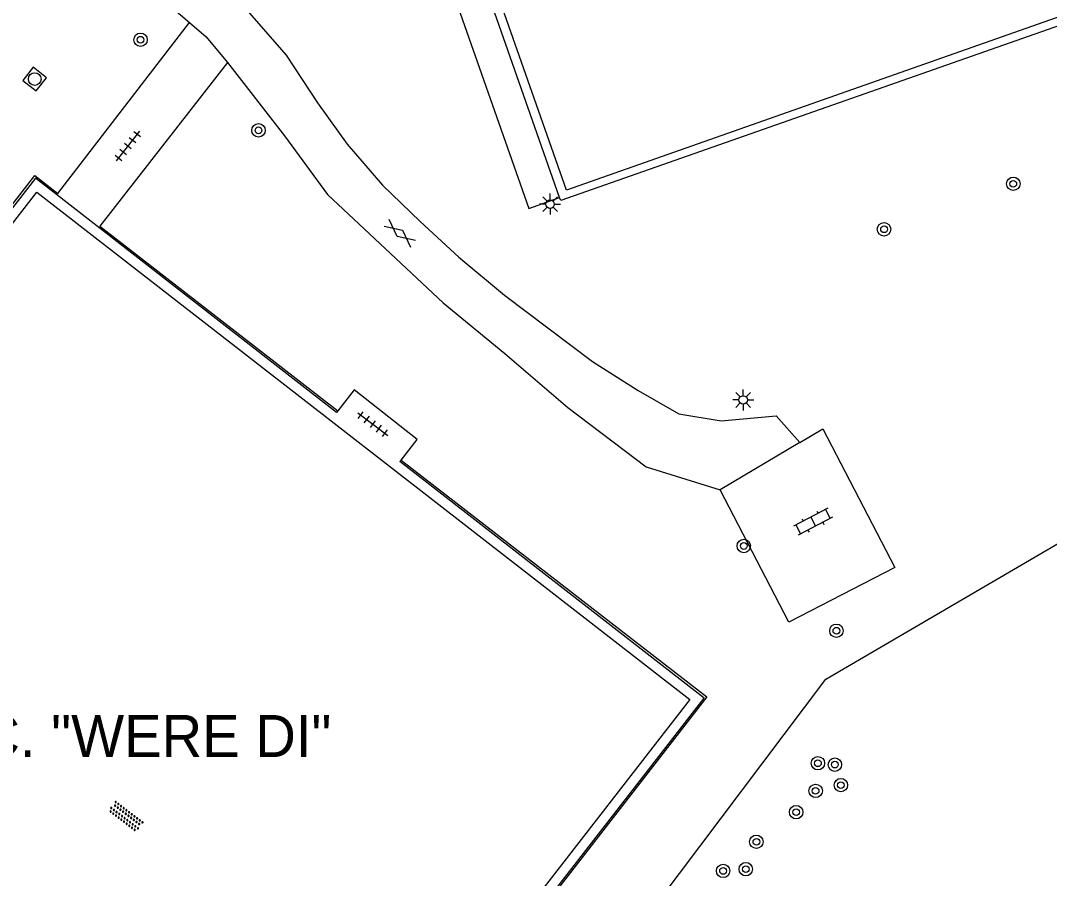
# Model space of a CAD drawing. Extents: x 135990 to 139000, y 393500 to 396000.
# Drawn here: x 136048.3 to 136109.5, y 395713.3 to 395764.3 of the extents above; entities that cross this region are included whole.
import ezdxf

# ---------------------------------------------------------------- set-up
doc = ezdxf.new("R2010")
doc.units = 0
for name, color, linetype in [('gg-afsc-hekwerk', 7, 'Continuous'), ('gg-knt-verharding', 7, 'Continuous'), ('gt-anno-naam bijzondere bebouwing', 7, 'Continuous'), ('gt-symb-boom', 7, 'Continuous'), ('gt-symb-gesloten verharding', 7, 'Continuous'), ('gt-symb-klinker verharding', 7, 'Continuous'), ('gt-symb-lichtmast', 7, 'Continuous'), ('gt-symb-overige verharding', 7, 'Continuous'), ('gt-symb-rioolschacht', 7, 'Continuous'), ('gt-symb-tegel verharding', 7, 'Continuous')]:
    doc.layers.add(name, color=color, linetype=linetype)

# ---------------------------------------------------------------- blocks, each defined once
blk = doc.blocks.new('gt0-BOOM')
at = {"layer": 'gt-symb-boom'}
for radius in [0.4, 0.2]:
    blk.add_circle((0, 0), radius, dxfattribs=at)
blk = doc.blocks.new('gt0-LMAST')
at = {"layer": 'gt-symb-lichtmast'}
for p, q in [((-0.005, 0.246), (-0.005, 0.621)), ((-0.182, 0.173), (-0.447, 0.438)), ((0.172, 0.173), (0.437, 0.438)), ((-0.255, -0.004), (-0.63, -0.004)), ((-0.182, -0.181), (-0.447, -0.446)), ((-0.005, -0.254), (-0.005, -0.629)), ((0.437, -0.446), (0.172, -0.181)), ((0.245, -0.004), (0.62, -0.004))]:
    blk.add_line(p, q, dxfattribs=at)
blk.add_circle((-0.005, -0.004), 0.25, dxfattribs=at)
blk = doc.blocks.new('gt0-KL1')
at = {"layer": 'gt-symb-klinker verharding'}
for p, q in [((-1.15, 0.3), (1.15, 0.3)), ((-1, -0.3), (-1, 0.3)), ((-0.5, 0.3), (-0.5, 0.45)), ((0, -0.3), (0, 0.3)), ((0.5, 0.3), (0.5, 0.45)), ((1, -0.3), (1, 0.3)), ((-1.15, -0.3), (1.15, -0.3)), ((-0.5, -0.45), (-0.5, -0.3)), ((0.5, -0.45), (0.5, -0.3))]:
    blk.add_line(p, q, dxfattribs=at)
blk = doc.blocks.new('gt0-GESVH1')
at = {"layer": 'gt-symb-gesloten verharding'}
for p, q in [((-0.992, -0.261), (0.008, 0.239)), ((0.008, -0.261), (-0.992, 0.239)), ((0.008, 0.239), (1.008, -0.261)), ((1.008, 0.239), (0.008, -0.261))]:
    blk.add_line(p, q, dxfattribs=at)
blk = doc.blocks.new('gt0-TEG1')
at = {"layer": 'gt-symb-tegel verharding'}
for p, q in [((-1.125, 0), (1.125, 0)), ((-0.9, -0.25), (-0.9, 0.25)), ((-0.45, -0.25), (-0.45, 0.25)), ((0, -0.25), (0, 0.25)), ((0.45, -0.25), (0.45, 0.25)), ((0.9, -0.25), (0.9, 0.25))]:
    blk.add_line(p, q, dxfattribs=at)
blk = doc.blocks.new('gt0-RS')
at = {"layer": 'gt-symb-rioolschacht'}
blk.add_lwpolyline([(-0.5, -0.5), (0.5, -0.5), (0.5, 0.5), (-0.5, 0.5)], close=True, dxfattribs=at)
blk.add_circle((0, 0), 0.375, dxfattribs=at)
blk = doc.blocks.new('gt0-OVH')
at = {"layer": 'gt-symb-overige verharding'}
for points in [[(-0.972, 0.298), (-0.967, 0.308), (-0.965, 0.319), (-0.966, 0.33), (-0.971, 0.34), (-0.978, 0.348), (-0.988, 0.353), (-0.999, 0.355), (-1.01, 0.354), (-1.02, 0.349), (-1.028, 0.342), (-1.033, 0.332), (-1.035, 0.321), (-1.034, 0.31), (-1.029, 0.3), (-1.022, 0.292), (-1.012, 0.287), (-1.001, 0.285), (-0.99, 0.286), (-0.98, 0.291)], [(-0.872, 0.106), (-0.867, 0.116), (-0.865, 0.126), (-0.866, 0.137), (-0.871, 0.147), (-0.878, 0.156), (-0.888, 0.161), (-0.899, 0.163), (-0.91, 0.162), (-0.92, 0.157), (-0.928, 0.15), (-0.933, 0.14), (-0.935, 0.129), (-0.934, 0.118), (-0.929, 0.108), (-0.922, 0.1), (-0.912, 0.095), (-0.901, 0.092), (-0.89, 0.094), (-0.88, 0.098)], [(-0.772, 0.298), (-0.767, 0.308), (-0.765, 0.319), (-0.766, 0.33), (-0.771, 0.34), (-0.778, 0.348), (-0.788, 0.353), (-0.799, 0.355), (-0.81, 0.354), (-0.82, 0.349), (-0.828, 0.342), (-0.833, 0.332), (-0.835, 0.321), (-0.834, 0.31), (-0.829, 0.3), (-0.822, 0.292), (-0.812, 0.287), (-0.801, 0.285), (-0.79, 0.286), (-0.78, 0.291)], [(-0.672, 0.106), (-0.667, 0.116), (-0.665, 0.126), (-0.666, 0.137), (-0.671, 0.147), (-0.678, 0.156), (-0.688, 0.161), (-0.699, 0.163), (-0.71, 0.162), (-0.72, 0.157), (-0.728, 0.15), (-0.733, 0.14), (-0.735, 0.129), (-0.734, 0.118), (-0.729, 0.108), (-0.722, 0.1), (-0.712, 0.095), (-0.701, 0.092), (-0.69, 0.094), (-0.68, 0.098)], [(-0.572, 0.298), (-0.567, 0.308), (-0.565, 0.319), (-0.566, 0.33), (-0.571, 0.34), (-0.578, 0.348), (-0.588, 0.353), (-0.599, 0.355), (-0.61, 0.354), (-0.62, 0.349), (-0.628, 0.342), (-0.633, 0.332), (-0.635, 0.321), (-0.634, 0.31), (-0.629, 0.3), (-0.622, 0.292), (-0.612, 0.287), (-0.601, 0.285), (-0.59, 0.286), (-0.58, 0.291)], [(-0.472, 0.106), (-0.467, 0.116), (-0.465, 0.126), (-0.466, 0.137), (-0.471, 0.147), (-0.478, 0.156), (-0.488, 0.161), (-0.499, 0.163), (-0.51, 0.162), (-0.52, 0.157), (-0.528, 0.15), (-0.533, 0.14), (-0.535, 0.129), (-0.534, 0.118), (-0.529, 0.108), (-0.522, 0.1), (-0.512, 0.095), (-0.501, 0.092), (-0.49, 0.094), (-0.48, 0.098)], [(-0.372, 0.298), (-0.367, 0.308), (-0.365, 0.319), (-0.366, 0.33), (-0.371, 0.34), (-0.378, 0.348), (-0.388, 0.353), (-0.399, 0.355), (-0.41, 0.354), (-0.42, 0.349), (-0.428, 0.342), (-0.433, 0.332), (-0.435, 0.321), (-0.434, 0.31), (-0.429, 0.3), (-0.422, 0.292), (-0.412, 0.287), (-0.401, 0.285), (-0.39, 0.286), (-0.38, 0.291)], [(-0.272, 0.106), (-0.267, 0.116), (-0.265, 0.126), (-0.266, 0.137), (-0.271, 0.147), (-0.278, 0.156), (-0.288, 0.161), (-0.299, 0.163), (-0.31, 0.162), (-0.32, 0.157), (-0.328, 0.15), (-0.333, 0.14), (-0.335, 0.129), (-0.334, 0.118), (-0.329, 0.108), (-0.322, 0.1), (-0.312, 0.095), (-0.301, 0.092), (-0.29, 0.094), (-0.28, 0.098)], [(-0.172, 0.298), (-0.167, 0.308), (-0.165, 0.319), (-0.166, 0.33), (-0.171, 0.34), (-0.178, 0.348), (-0.188, 0.353), (-0.199, 0.355), (-0.21, 0.354), (-0.22, 0.349), (-0.228, 0.342), (-0.233, 0.332), (-0.235, 0.321), (-0.234, 0.31), (-0.229, 0.3), (-0.222, 0.292), (-0.212, 0.287), (-0.201, 0.285), (-0.19, 0.286), (-0.18, 0.291)], [(-0.072, 0.106), (-0.067, 0.116), (-0.065, 0.126), (-0.066, 0.137), (-0.071, 0.147), (-0.078, 0.156), (-0.088, 0.161), (-0.099, 0.163), (-0.11, 0.162), (-0.12, 0.157), (-0.128, 0.15), (-0.133, 0.14), (-0.135, 0.129), (-0.134, 0.118), (-0.129, 0.108), (-0.122, 0.1), (-0.112, 0.095), (-0.101, 0.092), (-0.09, 0.094), (-0.08, 0.098)], [(0.028, 0.298), (0.033, 0.308), (0.035, 0.319), (0.034, 0.33), (0.029, 0.34), (0.022, 0.348), (0.012, 0.353), (0.001, 0.355), (-0.01, 0.354), (-0.02, 0.349), (-0.028, 0.342), (-0.033, 0.332), (-0.035, 0.321), (-0.034, 0.31), (-0.029, 0.3), (-0.022, 0.292), (-0.012, 0.287), (-0.001, 0.285), (0.01, 0.286), (0.02, 0.291)], [(0.128, 0.106), (0.133, 0.116), (0.135, 0.126), (0.134, 0.137), (0.129, 0.147), (0.122, 0.156), (0.112, 0.161), (0.101, 0.163), (0.09, 0.162), (0.08, 0.157), (0.072, 0.15), (0.067, 0.14), (0.065, 0.129), (0.066, 0.118), (0.071, 0.108), (0.078, 0.1), (0.088, 0.095), (0.099, 0.092), (0.11, 0.094), (0.12, 0.098)], [(0.228, 0.298), (0.233, 0.308), (0.235, 0.319), (0.234, 0.33), (0.229, 0.34), (0.222, 0.348), (0.212, 0.353), (0.201, 0.355), (0.19, 0.354), (0.18, 0.349), (0.172, 0.342), (0.167, 0.332), (0.165, 0.321), (0.166, 0.31), (0.171, 0.3), (0.178, 0.292), (0.188, 0.287), (0.199, 0.285), (0.21, 0.286), (0.22, 0.291)], [(0.328, 0.106), (0.333, 0.116), (0.335, 0.126), (0.334, 0.137), (0.329, 0.147), (0.322, 0.156), (0.312, 0.161), (0.301, 0.163), (0.29, 0.162), (0.28, 0.157), (0.272, 0.15), (0.267, 0.14), (0.265, 0.129), (0.266, 0.118), (0.271, 0.108), (0.278, 0.1), (0.288, 0.095), (0.299, 0.092), (0.31, 0.094), (0.32, 0.098)], [(0.428, 0.298), (0.433, 0.308), (0.435, 0.319), (0.434, 0.33), (0.429, 0.34), (0.422, 0.348), (0.412, 0.353), (0.401, 0.355), (0.39, 0.354), (0.38, 0.349), (0.372, 0.342), (0.367, 0.332), (0.365, 0.321), (0.366, 0.31), (0.371, 0.3), (0.378, 0.292), (0.388, 0.287), (0.399, 0.285), (0.41, 0.286), (0.42, 0.291)], [(0.528, 0.106), (0.533, 0.116), (0.535, 0.126), (0.534, 0.137), (0.529, 0.147), (0.522, 0.156), (0.512, 0.161), (0.501, 0.163), (0.49, 0.162), (0.48, 0.157), (0.472, 0.15), (0.467, 0.14), (0.465, 0.129), (0.466, 0.118), (0.471, 0.108), (0.478, 0.1), (0.488, 0.095), (0.499, 0.092), (0.51, 0.094), (0.52, 0.098)], [(0.628, 0.298), (0.633, 0.308), (0.635, 0.319), (0.634, 0.33), (0.629, 0.34), (0.622, 0.348), (0.612, 0.353), (0.601, 0.355), (0.59, 0.354), (0.58, 0.349), (0.572, 0.342), (0.567, 0.332), (0.565, 0.321), (0.566, 0.31), (0.571, 0.3), (0.578, 0.292), (0.588, 0.287), (0.599, 0.285), (0.61, 0.286), (0.62, 0.291)], [(0.728, 0.106), (0.733, 0.116), (0.735, 0.126), (0.734, 0.137), (0.729, 0.147), (0.722, 0.156), (0.712, 0.161), (0.701, 0.163), (0.69, 0.162), (0.68, 0.157), (0.672, 0.15), (0.667, 0.14), (0.665, 0.129), (0.666, 0.118), (0.671, 0.108), (0.678, 0.1), (0.688, 0.095), (0.699, 0.092), (0.71, 0.094), (0.72, 0.098)], [(0.828, 0.298), (0.833, 0.308), (0.835, 0.319), (0.834, 0.33), (0.829, 0.34), (0.822, 0.348), (0.812, 0.353), (0.801, 0.355), (0.79, 0.354), (0.78, 0.349), (0.772, 0.342), (0.767, 0.332), (0.765, 0.321), (0.766, 0.31), (0.771, 0.3), (0.778, 0.292), (0.788, 0.287), (0.799, 0.285), (0.81, 0.286), (0.82, 0.291)], [(0.928, 0.106), (0.933, 0.116), (0.935, 0.126), (0.934, 0.137), (0.929, 0.147), (0.922, 0.156), (0.912, 0.161), (0.901, 0.163), (0.89, 0.162), (0.88, 0.157), (0.872, 0.15), (0.867, 0.14), (0.865, 0.129), (0.866, 0.118), (0.871, 0.108), (0.878, 0.1), (0.888, 0.095), (0.899, 0.092), (0.91, 0.094), (0.92, 0.098)], [(1.028, 0.298), (1.033, 0.308), (1.035, 0.319), (1.034, 0.33), (1.029, 0.34), (1.022, 0.348), (1.012, 0.353), (1.001, 0.355), (0.99, 0.354), (0.98, 0.349), (0.972, 0.342), (0.967, 0.332), (0.965, 0.321), (0.966, 0.31), (0.971, 0.3), (0.978, 0.292), (0.988, 0.287), (0.999, 0.285), (1.01, 0.286), (1.02, 0.291)], [(-0.972, -0.142), (-0.967, -0.132), (-0.965, -0.121), (-0.966, -0.11), (-0.971, -0.1), (-0.978, -0.092), (-0.988, -0.087), (-0.999, -0.085), (-1.01, -0.086), (-1.02, -0.091), (-1.028, -0.098), (-1.033, -0.108), (-1.035, -0.119), (-1.034, -0.13), (-1.029, -0.14), (-1.022, -0.148), (-1.012, -0.153), (-1.001, -0.155), (-0.99, -0.154), (-0.98, -0.149)], [(-0.872, -0.334), (-0.867, -0.324), (-0.865, -0.314), (-0.866, -0.303), (-0.871, -0.293), (-0.878, -0.284), (-0.888, -0.279), (-0.899, -0.277), (-0.91, -0.278), (-0.92, -0.283), (-0.928, -0.29), (-0.933, -0.3), (-0.935, -0.311), (-0.934, -0.322), (-0.929, -0.332), (-0.922, -0.34), (-0.912, -0.345), (-0.901, -0.348), (-0.89, -0.346), (-0.88, -0.342)], [(-0.772, -0.142), (-0.767, -0.132), (-0.765, -0.121), (-0.766, -0.11), (-0.771, -0.1), (-0.778, -0.092), (-0.788, -0.087), (-0.799, -0.085), (-0.81, -0.086), (-0.82, -0.091), (-0.828, -0.098), (-0.833, -0.108), (-0.835, -0.119), (-0.834, -0.13), (-0.829, -0.14), (-0.822, -0.148), (-0.812, -0.153), (-0.801, -0.155), (-0.79, -0.154), (-0.78, -0.149)], [(-0.672, -0.334), (-0.667, -0.324), (-0.665, -0.314), (-0.666, -0.303), (-0.671, -0.293), (-0.678, -0.284), (-0.688, -0.279), (-0.699, -0.277), (-0.71, -0.278), (-0.72, -0.283), (-0.728, -0.29), (-0.733, -0.3), (-0.735, -0.311), (-0.734, -0.322), (-0.729, -0.332), (-0.722, -0.34), (-0.712, -0.345), (-0.701, -0.348), (-0.69, -0.346), (-0.68, -0.342)], [(-0.572, -0.142), (-0.567, -0.132), (-0.565, -0.121), (-0.566, -0.11), (-0.571, -0.1), (-0.578, -0.092), (-0.588, -0.087), (-0.599, -0.085), (-0.61, -0.086), (-0.62, -0.091), (-0.628, -0.098), (-0.633, -0.108), (-0.635, -0.119), (-0.634, -0.13), (-0.629, -0.14), (-0.622, -0.148), (-0.612, -0.153), (-0.601, -0.155), (-0.59, -0.154), (-0.58, -0.149)], [(-0.472, -0.334), (-0.467, -0.324), (-0.465, -0.314), (-0.466, -0.303), (-0.471, -0.293), (-0.478, -0.284), (-0.488, -0.279), (-0.499, -0.277), (-0.51, -0.278), (-0.52, -0.283), (-0.528, -0.29), (-0.533, -0.3), (-0.535, -0.311), (-0.534, -0.322), (-0.529, -0.332), (-0.522, -0.34), (-0.512, -0.345), (-0.501, -0.348), (-0.49, -0.346), (-0.48, -0.342)], [(-0.372, -0.142), (-0.367, -0.132), (-0.365, -0.121), (-0.366, -0.11), (-0.371, -0.1), (-0.378, -0.092), (-0.388, -0.087), (-0.399, -0.085), (-0.41, -0.086), (-0.42, -0.091), (-0.428, -0.098), (-0.433, -0.108), (-0.435, -0.119), (-0.434, -0.13), (-0.429, -0.14), (-0.422, -0.148), (-0.412, -0.153), (-0.401, -0.155), (-0.39, -0.154), (-0.38, -0.149)], [(-0.272, -0.334), (-0.267, -0.324), (-0.265, -0.314), (-0.266, -0.303), (-0.271, -0.293), (-0.278, -0.284), (-0.288, -0.279), (-0.299, -0.277), (-0.31, -0.278), (-0.32, -0.283), (-0.328, -0.29), (-0.333, -0.3), (-0.335, -0.311), (-0.334, -0.322), (-0.329, -0.332), (-0.322, -0.34), (-0.312, -0.345), (-0.301, -0.348), (-0.29, -0.346), (-0.28, -0.342)], [(-0.172, -0.142), (-0.167, -0.132), (-0.165, -0.121), (-0.166, -0.11), (-0.171, -0.1), (-0.178, -0.092), (-0.188, -0.087), (-0.199, -0.085), (-0.21, -0.086), (-0.22, -0.091), (-0.228, -0.098), (-0.233, -0.108), (-0.235, -0.119), (-0.234, -0.13), (-0.229, -0.14), (-0.222, -0.148), (-0.212, -0.153), (-0.201, -0.155), (-0.19, -0.154), (-0.18, -0.149)], [(-0.072, -0.334), (-0.067, -0.324), (-0.065, -0.314), (-0.066, -0.303), (-0.071, -0.293), (-0.078, -0.284), (-0.088, -0.279), (-0.099, -0.277), (-0.11, -0.278), (-0.12, -0.283), (-0.128, -0.29), (-0.133, -0.3), (-0.135, -0.311), (-0.134, -0.322), (-0.129, -0.332), (-0.122, -0.34), (-0.112, -0.345), (-0.101, -0.348), (-0.09, -0.346), (-0.08, -0.342)], [(0.028, -0.142), (0.033, -0.132), (0.035, -0.121), (0.034, -0.11), (0.029, -0.1), (0.022, -0.092), (0.012, -0.087), (0.001, -0.085), (-0.01, -0.086), (-0.02, -0.091), (-0.028, -0.098), (-0.033, -0.108), (-0.035, -0.119), (-0.034, -0.13), (-0.029, -0.14), (-0.022, -0.148), (-0.012, -0.153), (-0.001, -0.155), (0.01, -0.154), (0.02, -0.149)], [(0.128, -0.334), (0.133, -0.324), (0.135, -0.314), (0.134, -0.303), (0.129, -0.293), (0.122, -0.284), (0.112, -0.279), (0.101, -0.277), (0.09, -0.278), (0.08, -0.283), (0.072, -0.29), (0.067, -0.3), (0.065, -0.311), (0.066, -0.322), (0.071, -0.332), (0.078, -0.34), (0.088, -0.345), (0.099, -0.348), (0.11, -0.346), (0.12, -0.342)], [(0.228, -0.142), (0.233, -0.132), (0.235, -0.121), (0.234, -0.11), (0.229, -0.1), (0.222, -0.092), (0.212, -0.087), (0.201, -0.085), (0.19, -0.086), (0.18, -0.091), (0.172, -0.098), (0.167, -0.108), (0.165, -0.119), (0.166, -0.13), (0.171, -0.14), (0.178, -0.148), (0.188, -0.153), (0.199, -0.155), (0.21, -0.154), (0.22, -0.149)], [(0.328, -0.334), (0.333, -0.324), (0.335, -0.314), (0.334, -0.303), (0.329, -0.293), (0.322, -0.284), (0.312, -0.279), (0.301, -0.277), (0.29, -0.278), (0.28, -0.283), (0.272, -0.29), (0.267, -0.3), (0.265, -0.311), (0.266, -0.322), (0.271, -0.332), (0.278, -0.34), (0.288, -0.345), (0.299, -0.348), (0.31, -0.346), (0.32, -0.342)], [(0.428, -0.142), (0.433, -0.132), (0.435, -0.121), (0.434, -0.11), (0.429, -0.1), (0.422, -0.092), (0.412, -0.087), (0.401, -0.085), (0.39, -0.086), (0.38, -0.091), (0.372, -0.098), (0.367, -0.108), (0.365, -0.119), (0.366, -0.13), (0.371, -0.14), (0.378, -0.148), (0.388, -0.153), (0.399, -0.155), (0.41, -0.154), (0.42, -0.149)], [(0.528, -0.334), (0.533, -0.324), (0.535, -0.314), (0.534, -0.303), (0.529, -0.293), (0.522, -0.284), (0.512, -0.279), (0.501, -0.277), (0.49, -0.278), (0.48, -0.283), (0.472, -0.29), (0.467, -0.3), (0.465, -0.311), (0.466, -0.322), (0.471, -0.332), (0.478, -0.34), (0.488, -0.345), (0.499, -0.348), (0.51, -0.346), (0.52, -0.342)], [(0.628, -0.142), (0.633, -0.132), (0.635, -0.121), (0.634, -0.11), (0.629, -0.1), (0.622, -0.092), (0.612, -0.087), (0.601, -0.085), (0.59, -0.086), (0.58, -0.091), (0.572, -0.098), (0.567, -0.108), (0.565, -0.119), (0.566, -0.13), (0.571, -0.14), (0.578, -0.148), (0.588, -0.153), (0.599, -0.155), (0.61, -0.154), (0.62, -0.149)], [(0.728, -0.334), (0.733, -0.324), (0.735, -0.314), (0.734, -0.303), (0.729, -0.293), (0.722, -0.284), (0.712, -0.279), (0.701, -0.277), (0.69, -0.278), (0.68, -0.283), (0.672, -0.29), (0.667, -0.3), (0.665, -0.311), (0.666, -0.322), (0.671, -0.332), (0.678, -0.34), (0.688, -0.345), (0.699, -0.348), (0.71, -0.346), (0.72, -0.342)], [(0.828, -0.142), (0.833, -0.132), (0.835, -0.121), (0.834, -0.11), (0.829, -0.1), (0.822, -0.092), (0.812, -0.087), (0.801, -0.085), (0.79, -0.086), (0.78, -0.091), (0.772, -0.098), (0.767, -0.108), (0.765, -0.119), (0.766, -0.13), (0.771, -0.14), (0.778, -0.148), (0.788, -0.153), (0.799, -0.155), (0.81, -0.154), (0.82, -0.149)], [(0.928, -0.334), (0.933, -0.324), (0.935, -0.314), (0.934, -0.303), (0.929, -0.293), (0.922, -0.284), (0.912, -0.279), (0.901, -0.277), (0.89, -0.278), (0.88, -0.283), (0.872, -0.29), (0.867, -0.3), (0.865, -0.311), (0.866, -0.322), (0.871, -0.332), (0.878, -0.34), (0.888, -0.345), (0.899, -0.348), (0.91, -0.346), (0.92, -0.342)], [(1.028, -0.142), (1.033, -0.132), (1.035, -0.121), (1.034, -0.11), (1.029, -0.1), (1.022, -0.092), (1.012, -0.087), (1.001, -0.085), (0.99, -0.086), (0.98, -0.091), (0.972, -0.098), (0.967, -0.108), (0.965, -0.119), (0.966, -0.13), (0.971, -0.14), (0.978, -0.148), (0.988, -0.153), (0.999, -0.155), (1.01, -0.154), (1.02, -0.149)]]:
    blk.add_lwpolyline(points, close=True, dxfattribs=at)

msp = doc.modelspace()

# ---------------------------------------------------------------- linework, layer by layer
at = {"layer": 'gg-afsc-hekwerk'}
for p, q in [((136096.189, 395725.12), (136147.436, 395755.067)), ((136054.801, 395670.12), (136096.189, 395725.12))]:
    msp.add_line(p, q, dxfattribs=at)
for points in [[(136080.358, 395753.775), (136072.354, 395776.592), (136070.864, 395776.113), (136069.185, 395780.872), (136070.616, 395781.417), (136048.889, 395843.256)], [(136123.258, 395809.97), (136126.361, 395800.987), (136127.86, 395801.511), (136129.579, 395796.647), (136128.077, 395796.122), (136136.116, 395773.156), (136080.421, 395753.595), (136080.358, 395753.775)], [(136067.161, 395741.084), (136067.088, 395740.99), (136049.169, 395754.929), (136012.837, 395708.088), (136030.805, 395694.144), (136029.81, 395692.862), (136033.544, 395689.949), (136034.546, 395691.24), (136052.623, 395677.211), (136088.957, 395723.978), (136070.849, 395738.064), (136070.92, 395738.156)], [(136070.92, 395738.156), (136071.878, 395739.387), (136068.128, 395742.327), (136067.161, 395741.084)]]:
    msp.add_lwpolyline(points, dxfattribs=at)
at = {"layer": 'gg-knt-verharding'}
for p, q in [((136055.238, 395766.834), (136058.338, 395764.197)), ((136094.652, 395739.192), (136089.918, 395736.39))]:
    msp.add_line(p, q, dxfattribs=at)
for points in [[(136048.132, 395847.054), (136102.827, 395866.304), (136135.438, 395773.474), (136080.76, 395754.222), (136048.132, 395847.054)], [(136042.975, 395780.56), (136058.548, 395800.598), (136061.745, 395791.48), (136061.811, 395791.504), (136063.529, 395786.753), (136066.321, 395787.809), (136068.606, 395781.351), (136068.036, 395781.158), (136070.309, 395774.719), (136070.862, 395774.931), (136078.522, 395753.131), (136080.358, 395753.775)], [(136056.891, 395769.523), (136061.904, 395764.744), (136064.084, 395762.249), (136065.944, 395759.417), (136067.712, 395756.954), (136069.812, 395754.51), (136072.055, 395752.348), (136074.356, 395750.239), (136077.068, 395747.975), (136082.304, 395744.021), (136085.03, 395742.292), (136087.451, 395740.904), (136089.976, 395740.484), (136093.246, 395740.789), (136094.652, 395739.192)], [(136070.92, 395738.156), (136089.111, 395724.058), (136052.648, 395677.099), (136051.572, 395677.914), (136034.608, 395691.086), (136033.579, 395689.762), (136029.621, 395692.787), (136030.599, 395694.143), (136012.679, 395708.096), (136049.12, 395755.098), (136050.494, 395754.027), (136058.338, 395764.197)], [(136058.338, 395764.197), (136059.325, 395763.348), (136060.588, 395761.822)], [(136060.588, 395761.822), (136052.989, 395752.073), (136067.161, 395741.084)], [(136060.588, 395761.822), (136063.975, 395757.441), (136066.534, 395753.967), (136073.427, 395747.506), (136077.099, 395744.498), (136080.839, 395741.282), (136085.497, 395737.755), (136089.918, 395736.39)], [(136049.245, 395754.091), (136088.105, 395723.911), (136052.536, 395678.091), (136013.666, 395708.255), (136049.245, 395754.091)], [(136094.652, 395739.192), (136096.029, 395740.007), (136100.299, 395731.762), (136094.004, 395728.501), (136089.918, 395736.39)]]:
    msp.add_lwpolyline(points, dxfattribs=at)

# ---------------------------------------------------------------- block references
at = {"layer": 'gt-symb-boom'}
for p in [(136055.418, 395763.169), (136062.435, 395757.777), (136107.353, 395754.598), (136099.662, 395751.888), (136091.316, 395733.044), (136096.827, 395728), (136095.728, 395720.115), (136096.736, 395720.032), (136095.59, 395718.47), (136097.093, 395718.812), (136094.433, 395717.205), (136092.065, 395715.442), (136090.084, 395713.706), (136091.435, 395713.813)]:
    msp.add_blockref('gt0-BOOM', p, dxfattribs=at)
at = {"layer": 'gt-symb-gesloten verharding', "rotation": -38.25701687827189}
msp.add_blockref('gt0-GESVH1', (136070.849, 395751.661), dxfattribs=at)
at = {"layer": 'gt-symb-klinker verharding', "rotation": -152.53777281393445}
msp.add_blockref('gt0-KL1', (136095.435, 395734.488), dxfattribs=at)
at = {"layer": 'gt-symb-lichtmast'}
for p in [(136079.795, 395753.389), (136091.285, 395741.74)]:
    msp.add_blockref('gt0-LMAST', p, dxfattribs=at)
at = {"layer": 'gt-symb-overige verharding', "rotation": -37.282255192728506}
msp.add_blockref('gt0-OVH', (136054.541, 395716.944), dxfattribs=at)
at = {"layer": 'gt-symb-rioolschacht', "rotation": -38.21615232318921}
msp.add_blockref('gt0-RS', (136049.119, 395760.828), dxfattribs=at)
at = {"layer": 'gt-symb-tegel verharding'}
for p, rotation in [((136054.664, 395756.85), -128.09608536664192), ((136069.243, 395740.295), -36.91570677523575)]:
    msp.add_blockref('gt0-TEG1', p, dxfattribs=dict(at, rotation=rotation))

# ---------------------------------------------------------------- texts
at = {"layer": 'gt-anno-naam bijzondere bebouwing'}
msp.add_text('T.M.H.C. "WERE DI"', height=2.5, dxfattribs=at).set_placement((136035.799, 395720.487))

doc.saveas('drawing.dxf')
